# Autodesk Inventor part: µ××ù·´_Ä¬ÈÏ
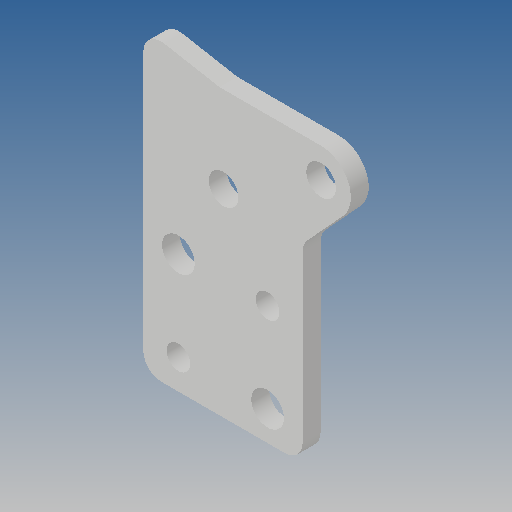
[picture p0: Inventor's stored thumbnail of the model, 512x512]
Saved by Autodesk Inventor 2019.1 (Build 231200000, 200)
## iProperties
Created: 2012-10
Part Number: µ××ù·´_Ä¬ÈÏ
Material: Ogólny
Document SubType Name: Modeling
Designer: CADENGINEERING4
Density: 1 g/cm^3
Appearance: Domyślna
Author: CADENGINEERING4
Revision Number: ÈÎºÎ
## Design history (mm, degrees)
feature "NONE"
node "Bryła1"
